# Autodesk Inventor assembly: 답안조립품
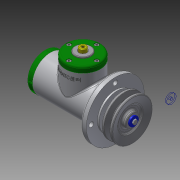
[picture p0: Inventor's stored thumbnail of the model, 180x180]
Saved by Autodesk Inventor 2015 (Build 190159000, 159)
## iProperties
Created: 2016-08
Part Number: 답안조립품
Document SubType Name: Assembly
Designer: owner
Author: owner
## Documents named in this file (25)
- C:\Users\owner\Desktop\460807V1004\답안조립품.iam
- C:\Users\owner\Desktop\460807V1004\본체.ipt
- C:\Users\owner\Desktop\460807V1004\탑 커버.ipt
- 탑 커버.ipt
- C:\Users\owner\Desktop\460807V1004\사이드 커버.ipt
- 사이드 커버.ipt
- C:\Users\owner\Desktop\460807V1004\볼트 M4 x 12.ipt
- C:\Users\owner\Desktop\460807V1004\탑 부시.ipt
- C:\Users\owner\Desktop\460807V1004\편심축.ipt
- C:\Users\owner\Desktop\460807V1004\부시1.ipt
- C:\Users\owner\Desktop\460807V1004\베어링 15 x 35 x 11.ipt
- C:\Users\owner\Desktop\460807V1004\멈춤링 35x1.6.ipt
- C:\Users\owner\Desktop\460807V1004\부시2.ipt
- C:\Users\owner\Desktop\460807V1004\와셔 10x21.ipt
- C:\Users\owner\Desktop\460807V1004\너트 M10.ipt
- C:\Users\owner\Desktop\460807V1004\멈춤링 15 x 1.ipt
- C:\Users\owner\Desktop\460807V1004\오일 실 15 25 7.ipt
- C:\Users\owner\Desktop\460807V1004\링크.ipt
- C:\Users\owner\Desktop\460807V1004\클래스터 핀 6 x 24.ipt
- C:\Users\owner\Desktop\460807V1004\슬라이더.ipt
- C:\Users\owner\Desktop\460807V1004\분할핀 1.6 x 12.ipt
- C:\Users\owner\Desktop\460807V1004\키 4 x 4 x 18.ipt
- C:\Users\owner\Desktop\460807V1004\V-벨트풀리.ipt
- C:\Users\owner\Desktop\460807V1004\와셔 4x16.ipt
- C:\Users\owner\Desktop\460807V1004\볼트 M4 x 10.ipt
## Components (6 placed, 3 different names)
1. V-벨트풀리:1
2. ISO 4017 M4 x 10:1
3. ISO 4762 M4 x 12:1
4. ISO 4762 M4 x 12:2
5. ISO 4762 M4 x 12:3
6. ISO 4762 M4 x 12:4
